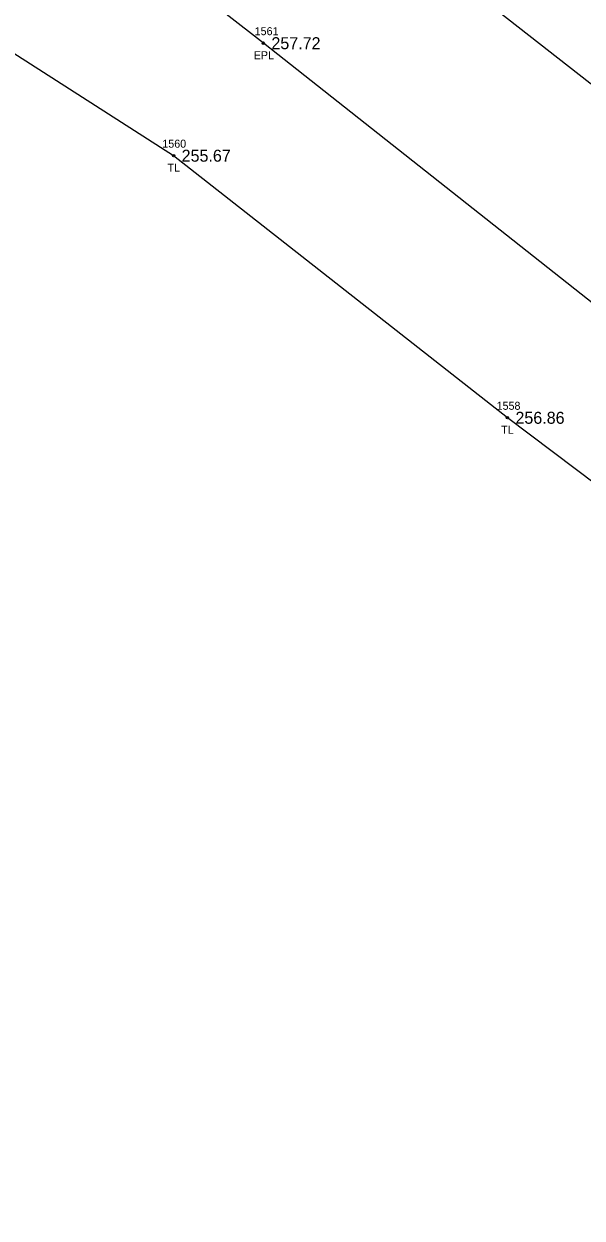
# Model space of a CAD drawing. Extents: x 1961231 to 1962574, y 799865 to 801120.
# Drawn here: x 1961508.5 to 1961578.2, y 800745.1 to 800894.4 of the extents above; entities that cross this region are included whole.
import ezdxf

# ---------------------------------------------------------------- set-up
doc = ezdxf.new("R2010")
doc.units = 0
for name, color, linetype in [('RD_EX_Road', 7, 'Continuous'), ('RD_EX_Road_txCode', 7, 'Continuous'), ('RD_EX_TX_Road_ELEV', 7, 'Continuous'), ('RD_EX_TX_VEG_ELEV', 7, 'Continuous'), ('RD_EX_VEG', 7, 'Continuous'), ('RD_EX_VEG_txCode', 7, 'Continuous'), ('RD_SMD_Locator', 7, 'Continuous')]:
    doc.layers.add(name, color=color, linetype=linetype)

msp = doc.modelspace()

# ---------------------------------------------------------------- linework, layer by layer
at = {"layer": 'RD_EX_Road'}
for points in [[(1961735.63, 800762.82), (1961702.92, 800788.52), (1961676.16, 800810.27), (1961651.45, 800830.73), (1961641.14, 800839.02), (1961595.18, 800874.45), (1961552.9, 800907.54), (1961510.92, 800940.49), (1961504.01, 800946.58), (1961476.53, 800968.16), (1961444.88, 800992.72), (1961406.41, 801021.23), (1961370.69, 801045.26)], [(1961722.95, 800745.11), (1961689.13, 800771.93), (1961670.14, 800787.03), (1961660.52, 800795.31), (1961637.49, 800813.67), (1961617.86, 800829), (1961581.48, 800857.91), (1961538.42, 800891.96), (1961505, 800917.96), (1961467.33, 800947.97), (1961432.02, 800975.33), (1961392.71, 801004.33), (1961360.06, 801026.78)]]:
    msp.add_lwpolyline(points, dxfattribs=at)
at = {"layer": 'RD_EX_VEG'}
msp.add_lwpolyline([(1961584.58, 800795.58), (1961602.69, 800819.62), (1961568.89, 800845.14), (1961527.21, 800877.9), (1961471.95, 800913.34)], dxfattribs=at)
at = {"layer": 'RD_SMD_Locator'}
for centre in [(1961538.42, 800891.96), (1961527.21, 800877.9), (1961568.89, 800845.14)]:
    msp.add_circle(centre, 0.15, dxfattribs=at)

# ---------------------------------------------------------------- texts
at = {"layer": 'RD_EX_Road_txCode'}
for s, p in [('1561', (1961537.33, 800892.96)), ('EPL', (1961537.21, 800889.96))]:
    msp.add_text(s, height=1, dxfattribs=at).set_placement(p)
at = {"layer": 'RD_EX_TX_Road_ELEV'}
msp.add_text('257.72', height=1.5, dxfattribs=at).set_placement((1961539.42, 800891.21))
at = {"layer": 'RD_EX_TX_VEG_ELEV'}
for s, p in [('255.67', (1961528.21, 800877.15)), ('256.86', (1961569.89, 800844.39))]:
    msp.add_text(s, height=1.5, dxfattribs=at).set_placement(p)
at = {"layer": 'RD_EX_VEG_txCode'}
for s, p in [('1560', (1961525.8, 800878.9)), ('TL', (1961526.44, 800875.9)), ('1558', (1961567.54, 800846.14)), ('TL', (1961568.11, 800843.14))]:
    msp.add_text(s, height=1, dxfattribs=at).set_placement(p)

doc.saveas('drawing.dxf')
